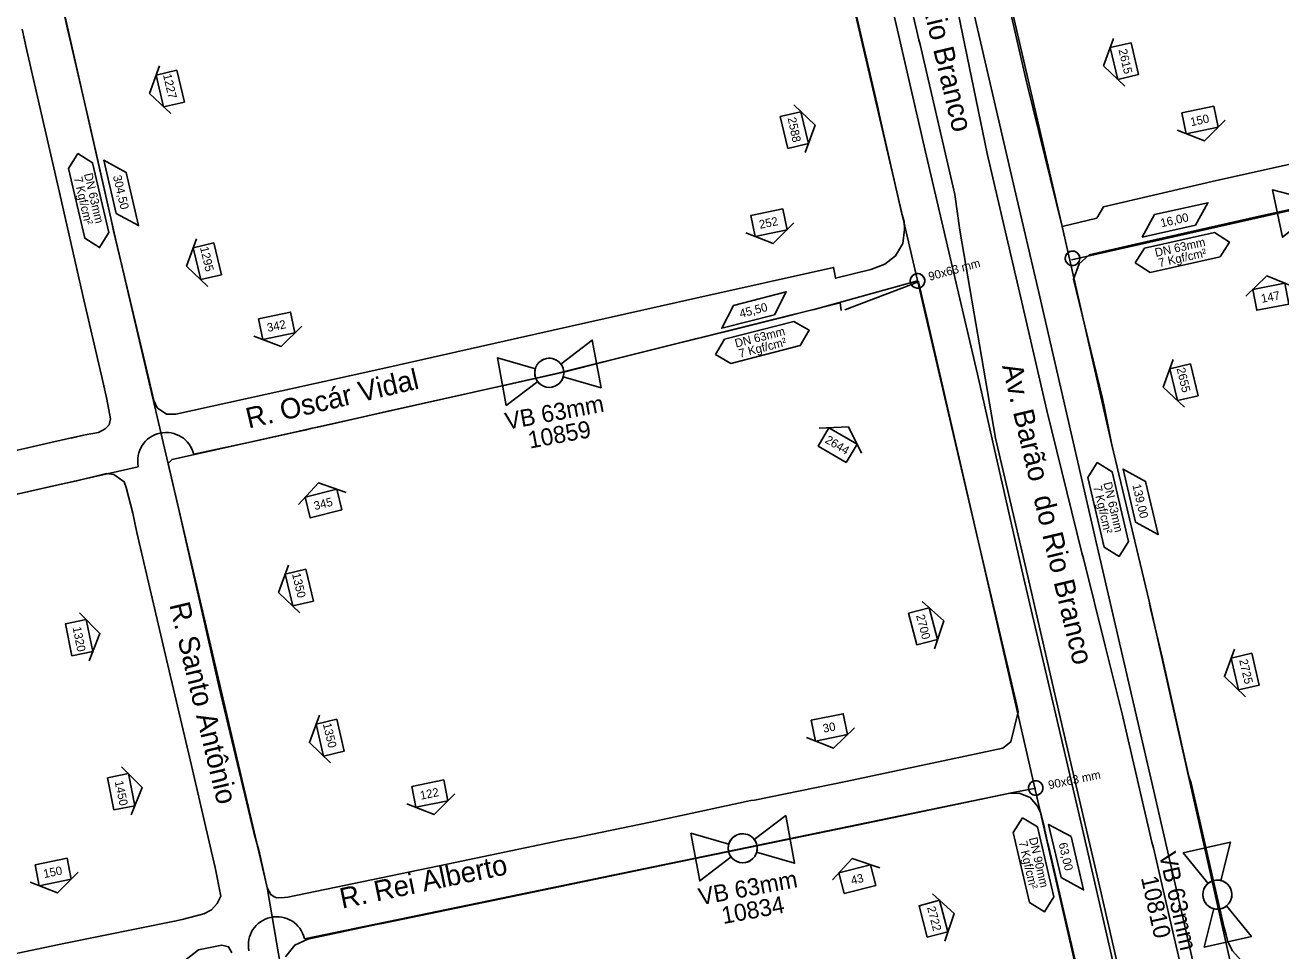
# Model space of a CAD drawing. Extents: x 656692 to 673945, y 7585994 to 7599066.
# Drawn here: x 670030 to 670472.2, y 7593036.1 to 7593362 of the extents above; entities that cross this region are included whole.
import ezdxf

# ---------------------------------------------------------------- set-up
doc = ezdxf.new("R2010")
doc.units = 0
for name, color, linetype in [('FORMATO', 7, 'Continuous'), ('LOGRADOURO', 7, 'Continuous'), ('LOGRADOURO_TEXTO', 7, 'Continuous'), ('NUM_REF', 7, 'Continuous'), ('SIMBOLO', 7, 'Continuous'), ('TEXTO', 7, 'Continuous'), ('TUBO_PEAD_GN_63', 7, 'Continuous'), ('TUBO_PEAD_GN_90', 7, 'Continuous'), ('VALVULA_PEAD_63', 7, 'Continuous')]:
    doc.layers.add(name, color=color, linetype=linetype)

# ---------------------------------------------------------------- blocks, each defined once
blk = doc.blocks.new('INTERLIGACAO_5')
at = {"layer": 'SIMBOLO'}
blk.add_circle((0, 0), 1.28, dxfattribs=at)
for start, end in [(0, 180), (180, 0)]:
    blk.add_arc((0, 0), 1.28, start, end, dxfattribs=at)
blk = doc.blocks.new('VALVULA_PEAD_DN_9')
at = {"layer": 'VALVULA_PEAD_63'}
for points in [[(-1.14, 0.57), (-4.25, 2.13), (-4.25, -2.13), (-1.14, -0.57)], [(-1.14, -0.57), (-4.25, -2.13), (-4.25, 2.13), (-1.14, 0.57)], [(1.14, -0.57), (4.25, -2.13), (4.25, 2.13), (1.14, 0.57)], [(1.14, -0.57), (4.25, -2.13), (4.25, 2.13), (1.14, 0.57)]]:
    blk.add_lwpolyline(points, dxfattribs=at)
blk.add_circle((0, 0), 1.28, dxfattribs=at)
for start, end in [(90, 270), (270, 90), (153.4349, 206.5651), (0, 26.5651), (333.4349, 0)]:
    blk.add_arc((0, 0), 1.28, start, end, dxfattribs=at)
blk = doc.blocks.new('NUM_REF_1')
at = {"layer": 'NUM_REF'}
blk.add_lwpolyline([(-4.3125, 0.9375), (0, 3.75), (4.3125, 0.9375)], dxfattribs=at)
blk.add_lwpolyline([(2.875, -1.875), (2.875, 1.875), (-2.875, 1.875), (-2.875, -1.875)], close=True, dxfattribs=at)

msp = doc.modelspace()

# ---------------------------------------------------------------- linework, layer by layer
at = {"layer": 'LOGRADOURO'}
for points in [[(670624.53, 7593346.32), (670569.73, 7593334.07), (670521.66, 7593323.42), (670475.94, 7593313.21), (670447.99, 7593307.01), (670409.67, 7593298.01), (670407.35, 7593294.02), (670395.17, 7593291.1), (670382.94, 7593340.67), (670382.41, 7593343.17), (670373.98, 7593379.53), (670373.43, 7593381.99), (670361.58, 7593433.22), (670360.99, 7593435.72), (670360.19, 7593440.5), (670361.29, 7593445.84), (670364.54, 7593449.36)], [(670370.49, 7593216.23), (670365.31, 7593239.19), (670356.94, 7593275.23), (670346.89, 7593317.85), (670337.18, 7593360.24), (670319.46, 7593435.91), (670320.05, 7593438.64), (670322.19, 7593439.95), (670324.67, 7593439.35), (670325.99, 7593437.38), (670344.66, 7593356.88), (670345.13, 7593355.18), (670357.38, 7593302.46), (670359.16, 7593289.89), (670371.72, 7593216.66), (670383.02, 7593167.92), (670394.57, 7593117.88), (670408.28, 7593058.99), (670415.84, 7593026.27)], [(670444.42, 7592998.48), (670434.11, 7593042.83), (670427.28, 7593072.47), (670426.73, 7593074.41), (670416.25, 7593119.64), (670410.29, 7593143.55), (670402.64, 7593174.3), (670402.12, 7593176.27), (670389.79, 7593226.4), (670380.92, 7593264.55), (670368.76, 7593316.87), (670345.18, 7593431.32)], [(670319.92, 7593377.44), (670330.4, 7593332.55), (670330.74, 7593330.63), (670338.76, 7593295.58), (670339.48, 7593292.94), (670339.69, 7593290.1), (670339.08, 7593285.18), (670336.51, 7593280.77), (670332.75, 7593277.87), (670327.79, 7593276.03), (670315.41, 7593272.92), (670315.11, 7593274.31), (670314.68, 7593276.72), (670266.19, 7593265.91), (670203.36, 7593251.86), (670157.07, 7593241.41), (670120.43, 7593233.24), (670083.07, 7593225.05), (670079.85, 7593225.05), (670076.53, 7593227.31), (670075.35, 7593229.86), (670073.29, 7593238.95), (670071.64, 7593245.81), (670061.92, 7593286.31), (670052.8, 7593326.83), (670045.39, 7593358.74), (670044.71, 7593361.7), (670042.62, 7593371.71)], [(670362.09, 7593374.99), (670378.38, 7593304.57), (670386.97, 7593267.93), (670397.07, 7593224.06), (670407.3, 7593179.59), (670415.31, 7593144.62), (670427.38, 7593092.32), (670438.58, 7593043.8), (670445.12, 7593015.02)], [(670042.11, 7593303.15), (670030.61, 7593353.08), (670028.97, 7593360.56)], [(670046.27, 7593216.68), (670051.22, 7593217.81), (670055.86, 7593218.63), (670058.25, 7593219.9), (670059.59, 7593221.28), (670060.08, 7593223.38), (670058.75, 7593230.32), (670057.18, 7593237.68), (670050.4, 7593266.86), (670042.11, 7593303.15)], [(670502.23, 7593302.97), (670464.67, 7593294.73), (670421.02, 7593284.97), (670404.62, 7593281.11), (670401.1, 7593278), (670399.17, 7593272.64), (670409.3, 7593230.6), (670409.98, 7593227.82), (670412.62, 7593214.31), (670425.77, 7593159.21), (670426.3, 7593156.69), (670430.32, 7593139.53), (670439.71, 7593097.51), (670440.58, 7593095.23), (670452.23, 7593044.22), (670452.89, 7593041.78), (670453.49, 7593039.34), (670455.1, 7593036.14), (670458.23, 7593032.8)], [(670318.68, 7593261.83), (670344.63, 7593271.71), (670347.76, 7593258), (670348.33, 7593255.49), (670366.09, 7593178.46), (670379.37, 7593122.05), (670379.69, 7593120.28), (670377.03, 7593109.71), (670374.29, 7593107.46), (670319, 7593095.73)], [(670319, 7593095.73), (670286.79, 7593089.22), (670285.53, 7593089.04), (670250.18, 7593081.45), (670222.39, 7593075.76), (670221.28, 7593075.57), (670178.62, 7593066.68), (670122.49, 7593055.04), (670121.39, 7593054.88), (670118.69, 7593054.82), (670117.76, 7593055.18), (670116.54, 7593055.94), (670115.31, 7593058.28), (670112.51, 7593070.61), (670110.61, 7593077.84), (670098.33, 7593128.86), (670085.07, 7593187.4), (670083.43, 7593194.61), (670080.37, 7593207.67), (670081.75, 7593209.16), (670141.72, 7593222.44), (670194.27, 7593234.23), (670217.17, 7593239.36), (670316.95, 7593264.21), (670317.37, 7593261.62)], [(670051.22, 7593217.81), (670046.35, 7593216.7), (670039.12, 7593215.13), (670000.26, 7593206.23)], [(670420.14, 7593001.27), (670402.29, 7593079.02), (670393.37, 7593117.27), (670381.6, 7593167.67), (670370.49, 7593216.23)], [(670080.25, 7593136.68), (670069.33, 7593183.43), (670067.93, 7593190.26), (670065.61, 7593199.25), (670064.87, 7593201.3), (670061.22, 7593203.78), (670058.67, 7593204.17), (670048.26, 7593201.66), (670041.07, 7593200.06), (670010.12, 7593193.09)], [(670044.25, 7593038.8), (670082.65, 7593046.6), (670085.32, 7593047.17), (670092.97, 7593049.13), (670095.62, 7593050.62), (670097.69, 7593052.83), (670098.94, 7593055.42), (670096.93, 7593065.46), (670095.54, 7593071.44), (670088.64, 7593101.43), (670080.25, 7593136.68)], [(670383.85, 7593090.08), (670380.01, 7593091.64), (670376.23, 7593091.56), (670323.55, 7593080.56), (670292.85, 7593074.2), (670256.85, 7593066.77), (670194.82, 7593053.91), (670156.28, 7593045.94), (670153.71, 7593045.41), (670129.59, 7593040.28), (670124.98, 7593038.17), (670121.66, 7593034.09)], [(670401.95, 7593023.23), (670390.41, 7593072.63), (670390.13, 7593073.88), (670389.04, 7593078.64), (670388.85, 7593079.96), (670387.55, 7593084.81), (670386.53, 7593087.12), (670383.85, 7593090.08)], [(669977.55, 7593024.93), (670044.25, 7593038.8)], [(670102.76, 7593035.48), (670101.69, 7593037.6), (670099.28, 7593038.12), (670091.11, 7593036.56), (670084.06, 7593030.95)]]:
    msp.add_lwpolyline(points, dxfattribs=at)
at = {"layer": 'SIMBOLO'}
for points in [[(670048.55, 7593316.84), (670053.8, 7593313.58), (670059.55, 7593288.99), (670056.28, 7593283.73), (670051.03, 7593287), (670045.28, 7593311.59), (670048.55, 7593316.84)], [(670420.87, 7593278.29), (670424.19, 7593283.51), (670448.83, 7593289), (670454.05, 7593285.68), (670450.74, 7593280.46), (670426.09, 7593274.97), (670420.87, 7593278.29)], [(670273.13, 7593246.1), (670276.28, 7593251.43), (670300.72, 7593257.73), (670306.05, 7593254.59), (670302.91, 7593249.26), (670278.46, 7593242.95), (670273.13, 7593246.1)], [(670407.45, 7593208.09), (670412.71, 7593204.83), (670418.47, 7593180.24), (670415.21, 7593174.99), (670409.95, 7593178.25), (670404.19, 7593202.83), (670407.45, 7593208.09)], [(670381.23, 7593083.03), (670386.48, 7593079.76), (670392.22, 7593055.17), (670388.96, 7593049.92), (670383.7, 7593053.18), (670377.96, 7593077.77), (670381.23, 7593083.03)]]:
    msp.add_lwpolyline(points, dxfattribs=at)
for points in [[(670062.07, 7593295.76), (670057.7, 7593314.47), (670065.64, 7593310.16), (670070.01, 7593291.45)], [(670442.09, 7593291.6), (670423.33, 7593287.42), (670427.72, 7593295.31), (670446.48, 7593299.49)], [(670293.9, 7593260.1), (670275.29, 7593255.3), (670279.41, 7593263.34), (670298.02, 7593268.14)], [(670420.99, 7593187.01), (670416.61, 7593205.73), (670424.55, 7593201.42), (670428.93, 7593182.71)], [(670394.75, 7593061.94), (670390.38, 7593080.66), (670398.32, 7593076.35), (670402.69, 7593057.63)]]:
    msp.add_lwpolyline(points, close=True, dxfattribs=at)
at = {"layer": 'TUBO_PEAD_GN_63'}
msp.add_line((670398.41, 7593279.43), (670712.13, 7593350.07), dxfattribs=at)
for points in [[(670270.63, 7593828.18), (670395.17, 7593291.1), (670412.62, 7593214.31), (670425.77, 7593159.21), (670458.65, 7593013.14)], [(670036.49, 7593394.84), (670042.62, 7593371.71), (670056.94, 7593308.46), (670060.28, 7593293.62), (670061.17, 7593289.64), (670063.93, 7593277.91), (670115.31, 7593058.49), (670129.76, 7592973.31), (670135.69, 7592949.71), (670140.2, 7592938.17), (670145.14, 7592928.13), (670154.31, 7592914.73), (670168.41, 7592898.93), (670188.86, 7592877.64), (670202.82, 7592863.12)], [(670138.39, 7593221.7), (670157.25, 7593225.99), (670183.16, 7593231.74), (670192.55, 7593233.84), (670199.11, 7593235.33), (670205.44, 7593236.72), (670220.13, 7593240.03), (670237.53, 7593244.44), (670257.71, 7593249.45), (670277.76, 7593254.43), (670296.56, 7593259.13), (670299.33, 7593259.82), (670301.48, 7593260.35), (670303.91, 7593260.96), (670306.17, 7593261.52), (670307.9, 7593261.96), (670344.23, 7593271.99)], [(670138.39, 7593221.7), (670135.65, 7593221.1), (670133.15, 7593220.55), (670131.09, 7593220.09), (670128.46, 7593219.5), (670125.71, 7593218.89), (670111.4, 7593215.72), (670089.4, 7593210.94)], [(670069.84, 7593206.59), (669981.87, 7593186.76), (669716.31, 7593127.44), (669704.58, 7593124.83)], [(670128.36, 7593040.43), (670377.91, 7593091.91), (670385.84, 7593093.47)]]:
    msp.add_lwpolyline(points, dxfattribs=at)
for centre in [(670079.67, 7593208.63), (670118.64, 7593038.18)]:
    msp.add_arc(centre, 10, 13.6027, 191.4515, dxfattribs=at)
at = {"layer": 'TUBO_PEAD_GN_90'}
msp.add_lwpolyline([(670197.11, 7593914.53), (670254.61, 7593659.28), (670299.9, 7593462.61), (670366.09, 7593178.46), (670413.3, 7592972.1)], dxfattribs=at)

# ---------------------------------------------------------------- block references
at = {"layer": 'FORMATO'}
for p, xscale, yscale, rotation in [((670417.06, 7593349.38), 2, 2, 103.25233689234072), ((670081.14, 7593339.7), 2, 2, 103.25233689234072), ((670300.86, 7593325.09), 2, 2, -76.67539240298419), ((670443.69, 7593328.6), 2, 2, -168.20476857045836), ((670291.9, 7593292.47), 2, 2, -168.20476857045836), ((670094.19, 7593278.88), 2, 2, 103.25233689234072), ((670468.62, 7593266.39), 2, 2, 10.786127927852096), ((670118.64, 7593256.18), 2, 2, -168.20476857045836), ((670438.04, 7593236.32), 2, 2, 103.25233689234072), ((670316.1, 7593214.16), 1.9999999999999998, 1.9999999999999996, -30.457932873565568), ((670135.11, 7593193.58), 1.9999999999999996, 1.9999999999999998, 14.110175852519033), ((670126.59, 7593164.01), 2, 2, 103.25233689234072), ((670346.19, 7593150.37), 2, 2, -75.27452059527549), ((670049.03, 7593146.37), 2, 2, -78.60070359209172), ((670459.59, 7593134.44), 2, 2, 103.25233689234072), ((670137.44, 7593111.2), 2, 2, 103.25233689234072), ((670313.21, 7593114.82), 2, 2, -168.497058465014), ((670063.86, 7593092.15), 2, 2, -78.60070359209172), ((670172.52, 7593091.5), 2, 2, -168.497058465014), ((670039.9, 7593063.92), 2, 2, -168.497058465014), ((670323.08, 7593061.43), 2, 2, 14.296656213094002), ((670349.85, 7593047.44), 2, 2, -75.27452059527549)]:
    msp.add_blockref('NUM_REF_1', p, dxfattribs=dict(at, xscale=xscale, yscale=yscale, rotation=rotation))
at = {"layer": 'SIMBOLO', "xscale": 2, "yscale": 2}
for p, rotation in [((670398.79, 7593279.92), -14.764722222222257), ((670344.23, 7593271.99), -141.4210614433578), ((670385.84, 7593093.48), 147.7759953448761)]:
    msp.add_blockref('INTERLIGACAO_5', p, dxfattribs=dict(at, rotation=rotation))
at = {"layer": 'VALVULA_PEAD_63'}
for p, xscale, yscale, rotation in [((670487.61, 7593299.24), 4.000000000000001, 4.000000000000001, -167.8897304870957), ((670214.58, 7593239.64), 3.9999999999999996, 4.000000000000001, 10.574770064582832), ((670282.68, 7593072.27), 3.9999999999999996, 4.000000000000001, 10.574770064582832), ((670449.8, 7593055.95), 4, 4, -77.45450238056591)]:
    msp.add_blockref('VALVULA_PEAD_DN_9', p, dxfattribs=dict(at, xscale=xscale, yscale=yscale, rotation=rotation))

# ---------------------------------------------------------------- texts
for s, height, rotation, p in [('2615', 3, 283.2523, (670414.98, 7593353.28)), ('1227', 3, 283.2523, (670078.55, 7593344.51)), ('150', 3, 11.7952, (670440.58, 7593326.42)), ('2588', 3, 281.8203, (670298.5, 7593329.27)), ('252', 3, 11.7952, (670288.78, 7593290.29)), ('1295', 3, 283.2523, (670091.59, 7593283.7)), ('90x63 mm', 3, 15.4386, (670348.52, 7593272.01)), ('147', 3, 10.7861, (670465.47, 7593264.26)), ('342', 3, 11.7952, (670115.53, 7593254)), ('2655', 3, 283.2523, (670435.44, 7593241.13)), ('VB 63mm', 6, 10.5748, (670199.61, 7593219.56)), ('10859', 6, 10.5748, (670207.71, 7593212.93)), ('2644', 3, 329.5421, (670311.41, 7593215.22)), ('345', 3, 14.1102, (670132.09, 7593191.27)), ('1350', 3, 283.2523, (670123.99, 7593168.83)), ('2700', 3, 284.7255, (670343.7, 7593154.17)), ('1320', 3, 281.3993, (670046.73, 7593149.98)), ('2725', 3, 283.2523, (670457.45, 7593138.51)), ('1350', 3, 283.2523, (670134.84, 7593116.02)), ('30', 3, 11.5029, (670311.22, 7593112.89)), ('1450', 3, 281.3993, (670061.57, 7593095.76)), ('90x63 mm', 3, 11.7966, (670390.59, 7593093.02)), ('122', 3, 11.5029, (670169.39, 7593089.33)), ('VB 63mm', 6, 282.5455, (670429.21, 7593070.22)), ('150', 3, 11.5029, (670036.77, 7593061.75)), ('VB 63mm', 6, 10.5748, (670267.72, 7593052.18)), ('43', 3, 14.2967, (670321.19, 7593059.4)), ('10810', 6, 282.5455, (670422.86, 7593061.89)), ('10834', 6, 10.5748, (670275.82, 7593045.56)), ('2722', 3, 284.7255, (670347.56, 7593051.42))]:
    msp.add_text(s, height=height, rotation=rotation).set_placement(p)
at = {"layer": 'LOGRADOURO_TEXTO'}
for s, rotation, p in [('Av. Barão  do Rio Branco', 283.441, (670331.52, 7593429.56)), ('Av. Barão  do Rio Branco', 283.441, (670373.95, 7593242.01)), ('R. Oscár Vidal', 13.1895, (670108.71, 7593220.01)), ('R. Santo Antônio', 283.5362, (670080.8, 7593158.02)), ('R. Rei Alberto', 11.746, (670141.63, 7593050.99))]:
    msp.add_text(s, height=7.2, rotation=rotation, dxfattribs=at).set_placement(p)
at = {"layer": 'TEXTO'}
for s, rotation, p in [('7 Kgf/cm²', 283.1431, (670047.16, 7593308.27)), ('DN 63mm', 283.1431, (670050.76, 7593309.58)), ('304,50', 283.1431, (670060.94, 7593308.86)), ('16,00', 12.5585, (670430.12, 7593290.85)), ('DN 63mm', 12.5585, (670428.15, 7593280.42)), ('7 Kgf/cm²', 12.5585, (670429.43, 7593276.82)), ('45,50', 14.4702, (670281.96, 7593258.96)), ('DN 63mm', 14.4702, (670280.34, 7593248.47)), ('7 Kgf/cm²', 14.4702, (670281.74, 7593244.91)), ('7 Kgf/cm²', 283.1838, (670406.07, 7593199.52)), ('DN 63mm', 283.1838, (670409.66, 7593200.83)), ('139,00', 283.1838, (670419.85, 7593200.11)), ('7 Kgf/cm²', 283.1431, (670379.84, 7593074.45)), ('DN 90mm', 283.1431, (670383.44, 7593075.77)), ('63,00', 283.1431, (670393.88, 7593073.91))]:
    msp.add_text(s, height=3, rotation=rotation, dxfattribs=at).set_placement(p)

doc.saveas('drawing.dxf')
